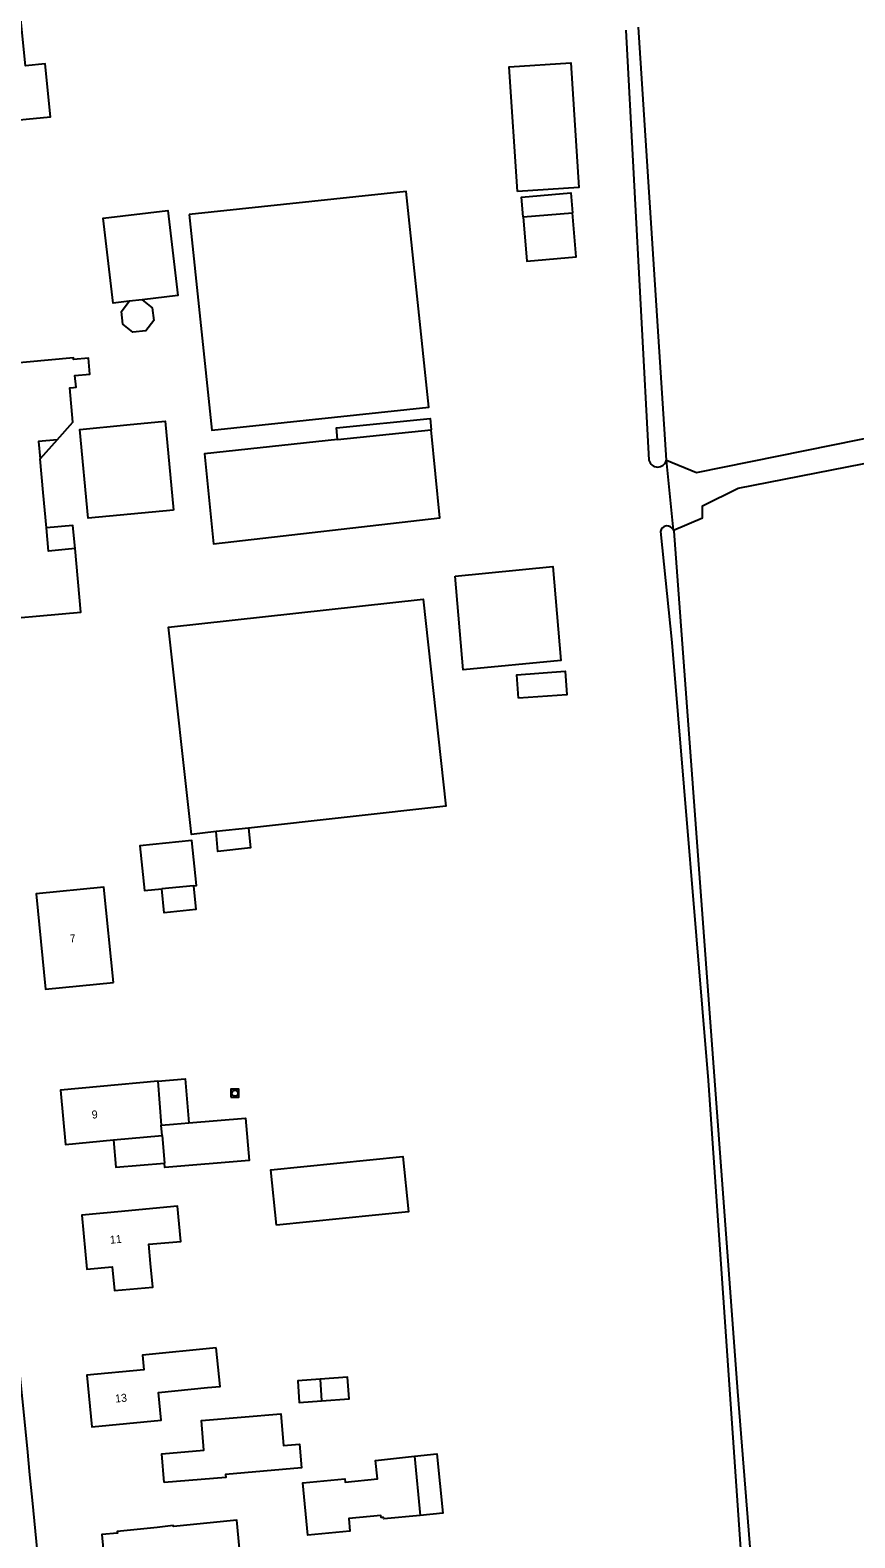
# Model space of a CAD drawing. Extents: x 140000 to 143000, y 403500 to 406000.
# Drawn here: x 140549.5 to 140652.7, y 404165.7 to 404354.5 of the extents above; entities that cross this region are included whole.
import ezdxf

# ---------------------------------------------------------------- set-up
doc = ezdxf.new("R2010")
doc.units = 0
for name, color, linetype in [('gg-anno-huisnummerreeks BGT', 7, 'Continuous'), ('gg-bbg-bijgebouw', 7, 'Continuous'), ('gg-bbg-hoofdgebouw', 7, 'Continuous'), ('gg-bbg-luifel en loopbrug', 7, 'Continuous'), ('gg-bbg-overig bouwwerk', 7, 'Continuous'), ('gg-bbg-tussenscheiding', 7, 'Continuous'), ('gg-knt-onverhard', 7, 'Continuous'), ('gg-knt-verharding', 7, 'Continuous'), ('gg-kntw-bovenkant insteek waterloop', 7, 'Continuous'), ('gt-symb-rioolschacht', 7, 'Continuous')]:
    doc.layers.add(name, color=color, linetype=linetype)

# ---------------------------------------------------------------- blocks, each defined once
blk = doc.blocks.new('gt0-RS')
at = {"layer": 'gt-symb-rioolschacht'}
blk.add_lwpolyline([(-0.5, -0.5), (0.5, -0.5), (0.5, 0.5), (-0.5, 0.5)], close=True, dxfattribs=at)
blk.add_circle((0, 0), 0.375, dxfattribs=at)

msp = doc.modelspace()

# ---------------------------------------------------------------- linework, layer by layer
at = {"layer": 'gg-bbg-bijgebouw'}
for p, q in [((140563.48, 404320.7), (140561.88, 404320.51)), ((140587.95, 404303.19), (140599.67, 404304.43)), ((140576.79, 404254.56), (140572.73, 404254.11)), ((140569.92, 404247.33), (140565.94, 404246.93)), ((140565.99, 404216.06), (140566.28, 404212.59)), ((140597.57, 404175.92), (140598.3, 404168.49))]:
    msp.add_line(p, q, dxfattribs=at)
for points in [[(140610.46, 404334.25), (140609.45, 404349.86), (140617.13, 404350.36), (140618.14, 404334.74), (140610.46, 404334.25)], [(140569.35, 404331.36), (140572.2, 404304.37), (140599.38, 404307.26), (140596.54, 404334.26), (140569.35, 404331.36)], [(140561.88, 404320.51), (140559.84, 404320.27), (140558.59, 404330.92), (140566.7, 404331.86), (140567.94, 404321.22), (140563.48, 404320.7)], [(140567.43, 404294.37), (140556.72, 404293.37), (140555.68, 404304.47), (140561.56, 404305.02), (140566.38, 404305.48), (140567.43, 404294.37)], [(140587.95, 404303.19), (140571.3, 404301.43), (140572.41, 404290.16), (140600.77, 404293.39), (140599.67, 404304.43)], [(140602.69, 404286.1), (140614.88, 404287.29), (140615.89, 404275.52), (140603.66, 404274.37), (140602.69, 404286.1)], [(140572.73, 404254.11), (140569.66, 404253.77), (140566.78, 404279.72), (140598.66, 404283.22), (140601.52, 404257.31), (140576.79, 404254.56)], [(140610.59, 404270.81), (140610.38, 404273.74), (140616.43, 404274.18), (140616.64, 404271.25), (140610.59, 404270.81)], [(140569.92, 404247.33), (140570.27, 404247.36), (140569.71, 404252.98), (140563.2, 404252.33), (140563.76, 404246.72), (140565.94, 404246.93)], [(140565.88, 404217.34), (140567.42, 404217.48), (140569.33, 404217.64)], [(140569.33, 404217.64), (140576.44, 404218.23), (140576.88, 404212.92), (140566.32, 404212.05), (140566.28, 404212.59)], [(140580.29, 404204.84), (140579.59, 404211.77), (140596.1, 404213.44), (140596.81, 404206.51), (140580.29, 404204.84)], [(140566.23, 404172.6), (140565.93, 404176.2), (140571.22, 404176.65), (140570.9, 404180.39), (140580.86, 404181.23), (140581.2, 404177.25), (140583.2, 404177.42), (140583.45, 404174.45), (140573.92, 404173.64), (140573.96, 404173.23), (140566.23, 404172.6)], [(140598.3, 404168.49), (140593.73, 404168.08), (140593.71, 404168.25), (140593.4, 404168.23), (140593.37, 404168.47), (140589.34, 404168.09), (140589.49, 404166.51), (140584.24, 404166.02), (140583.62, 404172.59), (140588.87, 404173.06), (140588.91, 404172.68), (140592.94, 404173.06), (140592.7, 404175.37), (140597.57, 404175.92)]]:
    msp.add_lwpolyline(points, dxfattribs=at)
at = {"layer": 'gg-bbg-hoofdgebouw'}
for p, q in [((140565.45, 404222.85), (140565.88, 404217.34)), ((140559.89, 404215.5), (140565.99, 404216.06))]:
    msp.add_line(p, q, dxfattribs=at)
for points in [[(140546.36, 404357.49), (140539.38, 404356.79), (140539.81, 404352.39), (140540.6, 404352.47), (140540.8, 404350.34), (140540.02, 404350.26), (140540.1, 404349.49), (140540.88, 404349.58), (140541.34, 404344.93), (140545.69, 404345.36), (140545.9, 404343), (140552.01, 404343.59), (140551.33, 404350.22), (140548.88, 404349.98), (140548.27, 404356.19), (140548.26, 404356.32)], [(140552.83, 404303.17), (140554.81, 404305.39), (140554.42, 404309.67), (140554.87, 404309.71), (140555.21, 404309.74), (140555.07, 404311.2), (140556.95, 404311.38), (140556.76, 404313.38), (140554.9, 404313.2), (140554.88, 404313.41), (140539.92, 404312.07), (140542.02, 404288.17), (140542.7, 404280.41), (140555.8, 404281.58), (140555.08, 404289.54)], [(140552.83, 404303.17), (140550.52, 404302.97), (140550.72, 404300.8)], [(140551.49, 404292.13), (140551.09, 404296.58), (140550.72, 404300.8)], [(140555.08, 404289.54), (140551.75, 404289.24), (140551.49, 404292.13)], [(140559.9, 404235.24), (140558.68, 404247.16), (140550.23, 404246.32), (140551.4, 404234.39), (140559.9, 404235.24)], [(140565.45, 404222.85), (140558.24, 404222.18), (140553.26, 404221.72), (140553.89, 404214.94), (140559.89, 404215.5)], [(140563.94, 404206.84), (140560.9, 404206.56), (140555.92, 404206.09), (140556.55, 404199.31), (140559.75, 404199.61), (140560.03, 404196.64), (140564.82, 404197.08), (140564.55, 404200.05), (140564.33, 404202.44), (140568.33, 404202.81), (140567.92, 404207.21), (140563.94, 404206.84)], [(140572.77, 404189.47), (140563.52, 404188.56), (140563.71, 404186.74), (140556.58, 404186.06), (140557.19, 404179.57), (140565.88, 404180.41), (140565.53, 404183.89), (140571.67, 404184.5), (140573.25, 404184.65), (140572.77, 404189.47)], [(140575.78, 404158.54), (140576.21, 404158.58), (140575.35, 404167.92), (140567.39, 404167.11), (140567.38, 404167.22), (140565.35, 404166.99), (140560.37, 404166.5), (140560.41, 404166.29), (140558.44, 404166.11), (140559.32, 404156.72)]]:
    msp.add_lwpolyline(points, dxfattribs=at)
at = {"layer": 'gg-bbg-luifel en loopbrug'}
for p, q in [((140611.18, 404331.07), (140617.35, 404331.6)), ((140552.83, 404303.17), (140550.72, 404300.8)), ((140585.75, 404185.56), (140585.95, 404182.84))]:
    msp.add_line(p, q, dxfattribs=at)
for points in [[(140611.18, 404331.07), (140611.66, 404325.54), (140617.83, 404326.07), (140617.35, 404331.6)], [(140587.95, 404303.19), (140587.8, 404304.68), (140599.53, 404305.84), (140599.67, 404304.43)], [(140555.08, 404289.54), (140554.82, 404292.43), (140551.49, 404292.13)], [(140576.79, 404254.56), (140577.03, 404252.07), (140572.97, 404251.62), (140572.73, 404254.11)], [(140569.92, 404247.33), (140570.22, 404244.34), (140566.24, 404243.95), (140565.94, 404246.93)], [(140565.45, 404222.85), (140568.87, 404223.17), (140569.33, 404217.64)], [(140559.89, 404215.5), (140560.2, 404212.08), (140566.28, 404212.59)], [(140585.75, 404185.56), (140582.96, 404185.36), (140583.15, 404182.64), (140585.95, 404182.84)], [(140597.57, 404175.92), (140600.39, 404176.19), (140601.12, 404168.76), (140598.3, 404168.49)]]:
    msp.add_lwpolyline(points, dxfattribs=at)
at = {"layer": 'gg-bbg-overig bouwwerk'}
for points in [[(140611.18, 404331.07), (140610.97, 404333.54), (140617.14, 404334.07), (140617.35, 404331.6)], [(140563.48, 404320.7), (140564.74, 404319.7), (140564.93, 404318.1), (140563.93, 404316.83), (140562.33, 404316.64), (140561.06, 404317.64), (140560.88, 404319.24), (140561.88, 404320.51)], [(140585.95, 404182.84), (140589.39, 404183.1), (140589.2, 404185.81), (140585.75, 404185.56)]]:
    msp.add_lwpolyline(points, dxfattribs=at)
at = {"layer": 'gg-bbg-tussenscheiding'}
msp.add_line((140565.99, 404216.06), (140565.88, 404217.34), dxfattribs=at)
at = {"layer": 'gg-knt-onverhard'}
msp.add_line((140630, 404291.87), (140629.11, 404300.61), dxfattribs=at)
for points in [[(140629.11, 404300.61), (140632.88, 404299.09), (140728.33, 404318.38), (140727.6, 404327.2)], [(140630, 404291.87), (140633.62, 404293.4), (140633.62, 404294.9), (140638.09, 404297.12), (140731.49, 404315.38), (140730.59, 404326.98)]]:
    msp.add_lwpolyline(points, dxfattribs=at)
at = {"layer": 'gg-knt-verharding'}
msp.add_lwpolyline([(140558.03, 404087.3), (140550.27, 404165.24), (140549.76, 404170.42), (140549.44, 404173.58), (140549.12, 404176.86), (140547.3, 404195.13), (140547.02, 404197.87), (140545.89, 404209.33), (140545.42, 404213.99), (140543.99, 404228.36), (140538.54, 404282.69)], dxfattribs=at)
at = {"layer": 'gg-kntw-bovenkant insteek waterloop'}
for p, q in [((140624.04, 404354.46), (140626.93, 404300.62)), ((140629.11, 404300.61), (140625.62, 404354.81))]:
    msp.add_line(p, q, dxfattribs=at)
for points in [[(140628.36, 404291.68), (140629.78, 404277.79), (140634.35, 404222.96), (140641.67, 404116.55)], [(140630, 404291.87), (140630.05, 404291.72), (140638.01, 404184.03), (140643.35, 404116.64)]]:
    msp.add_lwpolyline(points, dxfattribs=at)
for centre, radius, start, end in [((140628.02, 404300.88), 1.12, 193.2751, 345.7221), ((140629.21, 404291.53), 0.863, 22.9014, 170.4132)]:
    msp.add_arc(centre, radius, start, end, dxfattribs=at)

# ---------------------------------------------------------------- block references
at = {"layer": 'gt-symb-rioolschacht'}
msp.add_blockref('gt0-RS', (140575.1, 404221.36), dxfattribs=at)

# ---------------------------------------------------------------- texts
at = {"layer": 'gg-anno-huisnummerreeks BGT'}
for s, rotation, p in [('7', 5.6, (140554.46, 404240.21)), ('9', 5.3, (140557.22, 404218.17)), ('11', 5.3, (140559.49, 404202.5)), ('13', 5.4, (140560.14, 404182.62))]:
    msp.add_text(s, height=1, rotation=rotation, dxfattribs=at).set_placement(p)

doc.saveas('drawing.dxf')
